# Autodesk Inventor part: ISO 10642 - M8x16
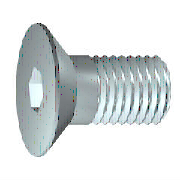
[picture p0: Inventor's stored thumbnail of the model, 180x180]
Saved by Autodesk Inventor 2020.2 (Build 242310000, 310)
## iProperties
Created: 2019-01
Part Number: ISO 10642 - M8x16
Material: Stahl, weich
Description: Senkschrauben mit Innensechskant
Document SubType Name: Modeling
Standard: ISO 10642
Designer: lutzd
Standards Organization: ISO
Language: de-DE
Size Designation: M8x16
Categories: <MemberInstance><Categories><Category DisplayName="Verbindungselemente" InternalName="e4da775c-781d-43d5-af7c-5136215cf5a6" Mnemonic="FSTN"><Category DisplayNam
Mass: 8.26098 g
Surface Area: 8.26631 cm^2
Volume: 1.05235 cm^3
Density: 7.85 g/cm^3
Appearance: Semi-Polished(8)
IsCustomPart: 0
Author: lutzd
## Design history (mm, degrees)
node "WorkPoint1"
sketch "Skizze2"
  geometry: L1 (-4, -16)-(0, -16); L2 (-4, -4.4)-(-4, -16); L3 (-8, -0.4)-(-4, -4.4); L4 (-8, 0)-(-8, -0.4); L5 (0, 0)-(-8, 0); L6 (0, -16)-(0, 0); L7 (0, -16)-(0, 0); L8 (0, -19.2)-(0, 3.2) reference; L9 (1.6, 0)-(-9.6, 0) reference
  constraints: 14 end point, 3 vertical, 2 horizontal
  dimensions: "d3" = 8 distance of L5.start L4.start (= 0.5 x dk); "d5" = 4 distance of L1.start L1.end (= 0.5 x NND); "d7" = 16 distance of L1.end L5.start (= NLG); "ParC" = 0.4 distance of L4.start L3.start; "d22" = 0 distance between parallel lines of L8 L6; "d23" = 0 distance between parallel lines of L9 L5; "d43" = 45 deg angle of L6 L3 (= 0.5 x ang)
revolve "Drehung1" stored, may be unused: angle "d8" = 360 deg
node "MSC_A1"
node "MSC_PF1"
node "MSC_PT1"
body "Solid1"
node "Skizze1"
sketch "Skizze3"
  geometry: L1 (-2.5, 1.443)-(-2.5, -1.443); L2 (0, 2.887)-(-2.5, 1.443); L3 (2.5, 1.443)-(0, 2.887); L4 (2.5, -1.443)-(2.5, 1.443); L5 (0, -2.887)-(2.5, -1.443); L6 (-2.5, -1.443)-(0, -2.887); C1 r 2.5 at (0, 0); C2 r 4 at (0, 0) reference
  constraints: 12 end point, 6 tangent, 2 parallel, 2 vertical, 1 centre point, 1 concentric
  dimensions: "d11" = 5 diameter of C1 (= ParS); "d13" = 120 deg angle of L1 L2; "d15" = 120 deg angle of L6 L1
extrude "Extrusion1" cut sketch "Skizze3" distance "d16" = 3.5 (= ParT); taper "d17" = 0 deg
fillet "Rundung1" dims "d18" = 0.5 (= r)
chamfer "Fase1" distance "d19" = 0.625 (= 0.5 x PTC); stored, may be unused: angle "d20" = 45 deg, second distance "d39" = 0.625 (= 0.5 x PTC)
feature "Gewinde1" dims "d35" = 0, "b" = 9.1
other parameters: "NND" = 8 [user parameter; used in 2 equation terms], "PTC" = 1.25 [user parameter; used in 2 equation terms], "dk" = 16 [user parameter; used in 1 equation term], "ParK" = 4.4 [user parameter], "ParS" = 5 [user parameter; used in 1 equation term], "ParT" = 3.5 [user parameter; used in 1 equation term], "r" = 0.5 [user parameter; used in 1 equation term], "NLG" = 16 [user parameter; used in 1 equation term], "d0" = 45 deg (derived), "d2" = 3 (derived), "d4" = 1.5 (derived), "d6" = 8 (derived), "d9" = 0, "d10" = 2 (derived), "d12" = 120 deg (derived), "d14" = 120 deg (derived), "d37" = 0, "d38" = 0, "d40" = 0, "d41" = 0, "d42" = 0, "ang" = 90 deg [user parameter; used in 1 equation term], "THREADDIA" = 8 (= NND) [user parameter]
